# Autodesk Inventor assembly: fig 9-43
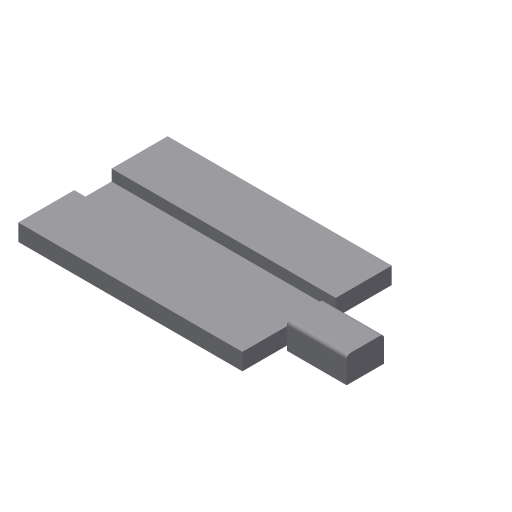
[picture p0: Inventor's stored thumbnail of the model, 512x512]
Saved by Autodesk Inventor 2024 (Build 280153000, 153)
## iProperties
Created: 2013-07
Part Number: fig 9-43
Document SubType Name: Assembly
Designer: CADCIM
Author: CADCIM
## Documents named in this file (3)
- D:\PROJECTS\Project 2023\RESOURCES INVENTOR 2024\RESOURCES INVENTOR 2024\Inventor_2023_Part\Inventor_2024_Part\c09_Inv_2024_prt\fig 9-44.iam
- D:\PROJECTS\Project 2023\RESOURCES INVENTOR 2024\RESOURCES INVENTOR 2024\Inventor_2023_Part\Inventor_2024_Part\c09_Inv_2024_prt\15.ipt
- D:\PROJECTS\Project 2023\RESOURCES INVENTOR 2024\RESOURCES INVENTOR 2024\Inventor_2023_Part\Inventor_2024_Part\c09_Inv_2024_prt\16.ipt
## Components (2 placed, 2 different names)
1. 15:1
2. 16:1
